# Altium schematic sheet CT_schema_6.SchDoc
size 218 x 258 mm
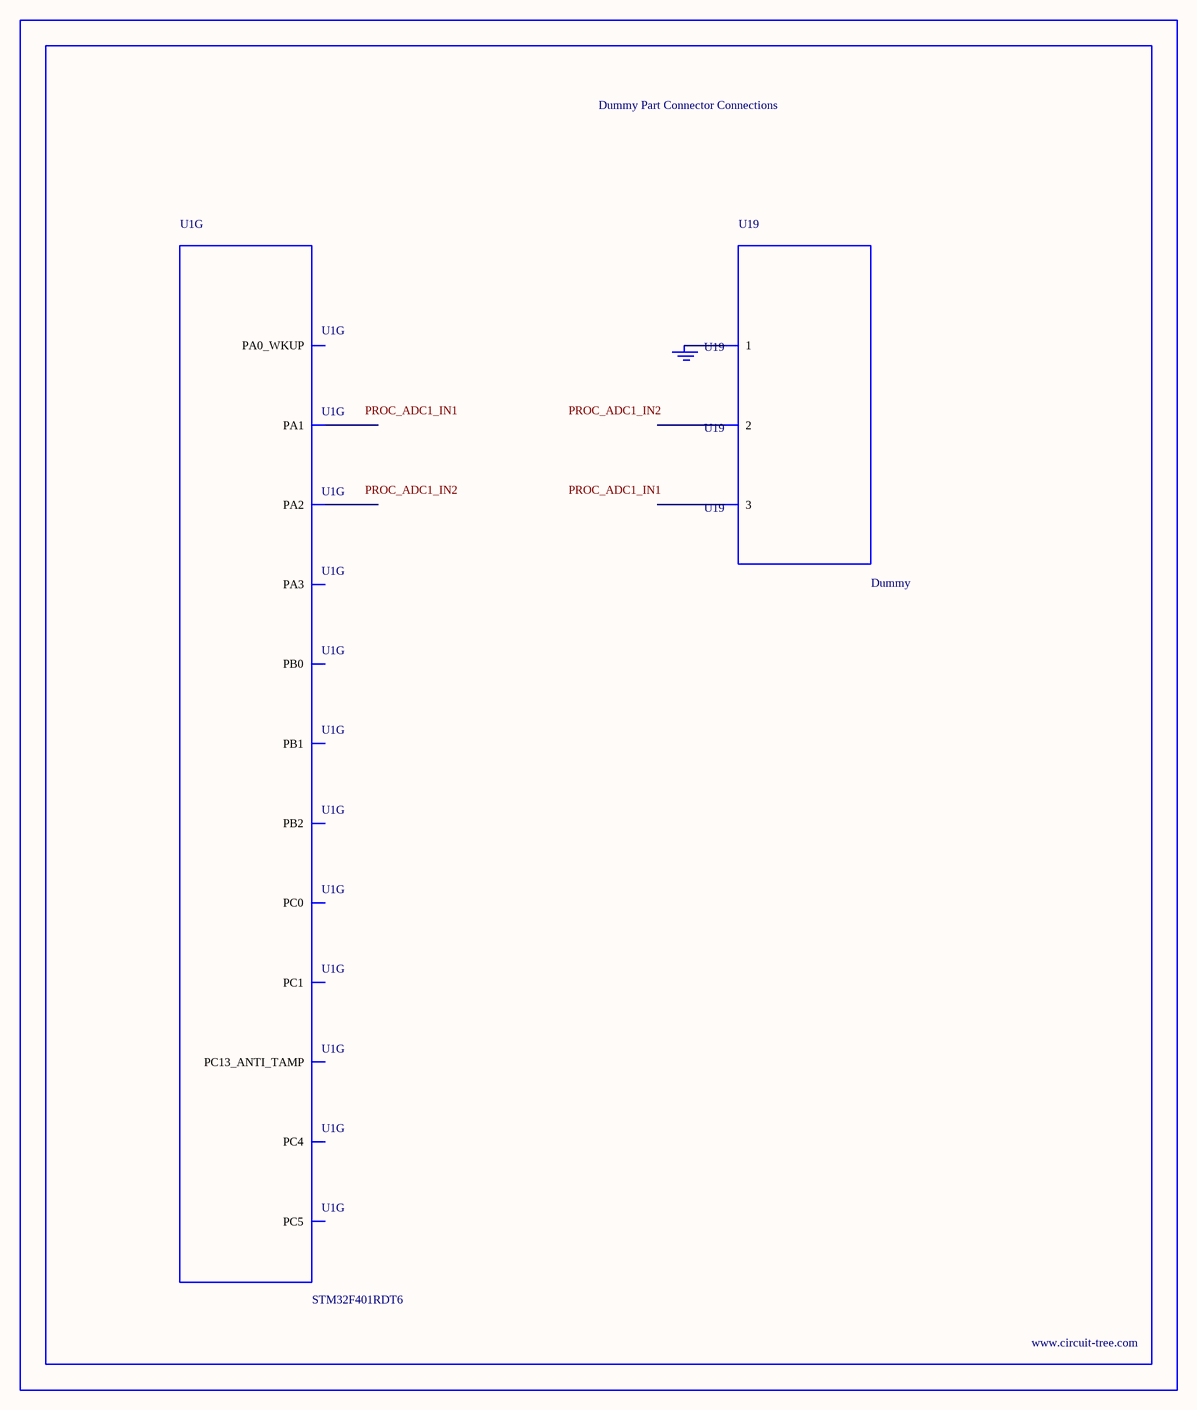
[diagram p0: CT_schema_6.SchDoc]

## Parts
BORDER5  (no value)
GND_INSTANCE_5_0  (no value)
U1  STM32F401RDT6  [LQFP64]  (part G of 7)
U19  Dummy  [DUMMY_PACKAGE_195]

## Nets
NetGND_INSTANCE_5_0_0: GND_INSTANCE_5_0.0(GND) U19.1

Not connected (* = marked no-connect by the designer): U1 2(PC13_ANTI_TAMP) 8(PC0) 9(PC1) 14(PA0_WKUP) 15(PA1) 16(PA2) 17(PA3) 24(PC4) 25(PC5) 26(PB0) 27(PB1) 28(PB2); U19 2 3

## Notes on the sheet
- Labels drawn without touching a wire or pin: PROC_ADC1_IN1, PROC_ADC1_IN2

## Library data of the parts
BORDER5 = BORDER_PAGE5
GND_INSTANCE_5_0 = GND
